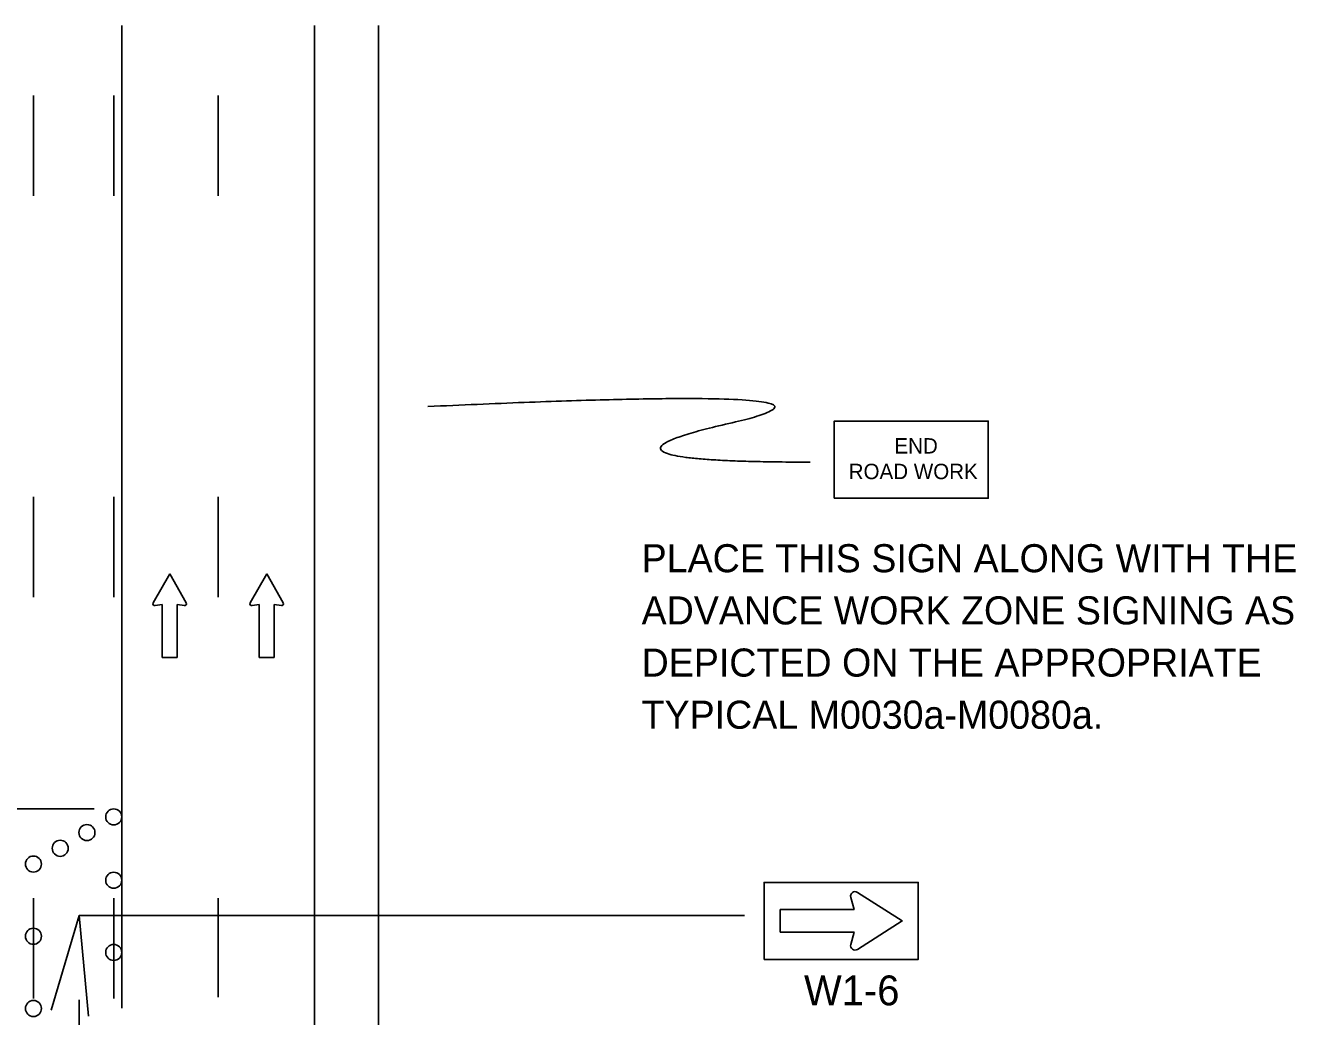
# Model space of a CAD drawing. Extents: x 16748 to 18475, y 7008 to 8262.
# Drawn here: x 17041.1 to 17357.5, y 7939 to 8186 of the extents above; entities that cross this region are included whole.
import ezdxf

# ---------------------------------------------------------------- set-up
doc = ezdxf.new("R2010")
doc.units = 0
for name, color, linetype in [('ALI_LEGAL_EX', 7, 'Continuous'), ('MT_SCRATCH_LEVEL_E', 7, 'Continuous'), ('PAVT_EDGE_EX', 7, 'Continuous'), ('TRAFFIC_SIGNS_PR', 7, 'Continuous'), ('TYPICAL_TEXT_DIMEN_PR', 7, 'Continuous')]:
    doc.layers.add(name, color=color, linetype=linetype)

msp = doc.modelspace()

# ---------------------------------------------------------------- linework, layer by layer
at = {"layer": 'ALI_LEGAL_EX'}
for points in [[(17043.08, 8168.47), (17043.08, 8143.47)], [(17063.08, 8168.47), (17063.08, 8143.47)], [(17089.08, 8168.47), (17089.08, 8143.47)], [(17043.08, 8068.47), (17043.08, 8043.47)], [(17063.08, 8068.47), (17063.08, 8043.47)], [(17089.08, 8068.47), (17089.08, 8043.47)], [(17043.08, 7968.47), (17043.08, 7943.47)], [(17063.08, 7968.47), (17063.08, 7943.47)], [(17089.08, 7968.47), (17089.08, 7943.81)]]:
    msp.add_lwpolyline(points, dxfattribs=at)
at = {"layer": 'MT_SCRATCH_LEVEL_E'}
for p, q in [((17077.02, 8049.3), (17072.9, 8042.06)), ((17077.02, 8049.3), (17072.9, 8042.06)), ((17081.16, 8042.06), (17077.02, 8049.3)), ((17081.16, 8042.06), (17077.02, 8049.3)), ((17101.19, 8049.3), (17097.08, 8042.06)), ((17101.19, 8049.3), (17097.08, 8042.06)), ((17105.33, 8042.06), (17101.19, 8049.3)), ((17105.33, 8042.06), (17101.19, 8049.3)), ((17073.39, 8041.37), (17075.16, 8041.69)), ((17073.39, 8041.37), (17075.16, 8041.69)), ((17075.16, 8041.69), (17075.16, 8028.43)), ((17075.16, 8041.69), (17075.16, 8028.43)), ((17078.91, 8028.43), (17078.91, 8041.69)), ((17078.91, 8041.69), (17080.68, 8041.37)), ((17078.91, 8028.43), (17078.91, 8041.69)), ((17078.91, 8041.69), (17080.68, 8041.37)), ((17097.56, 8041.37), (17099.33, 8041.69)), ((17097.56, 8041.37), (17099.33, 8041.69)), ((17099.33, 8041.69), (17099.33, 8028.43)), ((17099.33, 8041.69), (17099.33, 8028.43)), ((17103.08, 8028.43), (17103.08, 8041.69)), ((17103.08, 8041.69), (17104.85, 8041.37)), ((17103.08, 8028.43), (17103.08, 8041.69)), ((17103.08, 8041.69), (17104.85, 8041.37)), ((17075.16, 8028.43), (17078.91, 8028.43)), ((17075.16, 8028.43), (17078.91, 8028.43)), ((17099.33, 8028.43), (17103.08, 8028.43)), ((17099.33, 8028.43), (17103.08, 8028.43))]:
    msp.add_line(p, q, dxfattribs=at)
for centre, start, end in [((17073.31, 8041.83), 150.4248, 279.9638), ((17073.31, 8041.83), 150.4248, 279.9638), ((17080.75, 8041.83), 260.0362, 29.7731), ((17080.75, 8041.83), 260.0362, 29.7731), ((17097.48, 8041.83), 150.4248, 279.9638), ((17097.48, 8041.83), 150.4248, 279.9638), ((17104.92, 8041.83), 260.0362, 29.7731), ((17104.92, 8041.83), 260.0362, 29.7731)]:
    msp.add_arc(centre, 0.463, start, end, dxfattribs=at)
at = {"layer": 'PAVT_EDGE_EX'}
for p, q in [((17065.08, 8185.96), (17065.08, 7941.02)), ((17113.08, 8185.96), (17113.08, 7352.54)), ((17129.08, 8185.96), (17129.08, 7352.54))]:
    msp.add_line(p, q, dxfattribs=at)
at = {"layer": 'TRAFFIC_SIGNS_PR'}
for p, q in [((17247.5, 7965.61), (17246.66, 7968.67)), ((17248.34, 7969.91), (17259.5, 7962.81)), ((17229.1, 7965.61), (17247.5, 7965.61)), ((17229.1, 7965.61), (17229.1, 7960.01)), ((17259.5, 7962.81), (17248.34, 7955.71)), ((17247.5, 7960.01), (17229.1, 7960.01)), ((17246.66, 7956.95), (17247.5, 7960.01))]:
    msp.add_line(p, q, dxfattribs=at)
for points in [[(17242.55, 8068.14), (17280.95, 8068.14), (17280.95, 8087.34), (17242.55, 8087.34)], [(17225.1, 7953.21), (17263.5, 7953.21), (17263.5, 7972.41), (17225.1, 7972.41)]]:
    msp.add_lwpolyline(points, close=True, dxfattribs=at)
for points in [[(17246.66, 7968.67), (17247.5, 7965.61), (17229.1, 7965.61), (17229.1, 7960.01), (17247.5, 7960.01), (17246.66, 7956.95)], [(17248.34, 7955.71), (17259.5, 7962.81), (17248.34, 7969.91)]]:
    msp.add_lwpolyline(points, dxfattribs=at)
for centre in [(17063.08, 7988.72), (17056.41, 7984.81), (17049.75, 7980.89), (17043.08, 7976.97), (17063.08, 7972.94), (17043.08, 7958.97), (17063.08, 7954.94), (17043.08, 7940.97)]:
    msp.add_circle(centre, 2, dxfattribs=at)
for centre, start, end in [((17247.74, 7968.97), 57.5304, 195.3269), ((17247.74, 7968.97), 57.5304, 195.3269), ((17247.74, 7956.65), 164.6731, 302.4696), ((17247.74, 7956.65), 164.6731, 302.4696)]:
    msp.add_arc(centre, 1.12, start, end, dxfattribs=at)
msp.add_open_spline([(17236.6, 8077.13), (17173.96, 8077.13), (17258.98, 8096.47), (17141.35, 8090.98)], degree=2, dxfattribs=at)
at = {"layer": 'TYPICAL_TEXT_DIMEN_PR'}
for p, q in [((17058.17, 7990.72), (16927.98, 7990.72)), ((17047.53, 7940.56), (17054.46, 7964.13)), ((17054.46, 7964.13), (17220.2, 7964.13)), ((17054.46, 7964.13), (17056.84, 7939.07)), ((17054.46, 7935.37), (17054.46, 7943.16))]:
    msp.add_line(p, q, dxfattribs=at)

# ---------------------------------------------------------------- texts
at = {"layer": 'TRAFFIC_SIGNS_PR'}
for s, height, p in [('END', 3.831, (17257.55, 8079.27)), ('ROAD WORK', 3.831, (17246.16, 8072.89)), ('PLACE THIS SIGN ALONG WITH THE', 7, (17194.58, 8049.68)), ('ADVANCE WORK ZONE SIGNING AS', 7, (17194.58, 8036.68)), ('DEPICTED ON THE APPROPRIATE', 7, (17194.58, 8023.68)), ('TYPICAL M0030a-M0080a.', 7, (17194.58, 8010.68)), ('W1-6', 7.44, (17235.04, 7941.77))]:
    msp.add_text(s, height=height, dxfattribs=at).set_placement(p)

doc.saveas('drawing.dxf')
